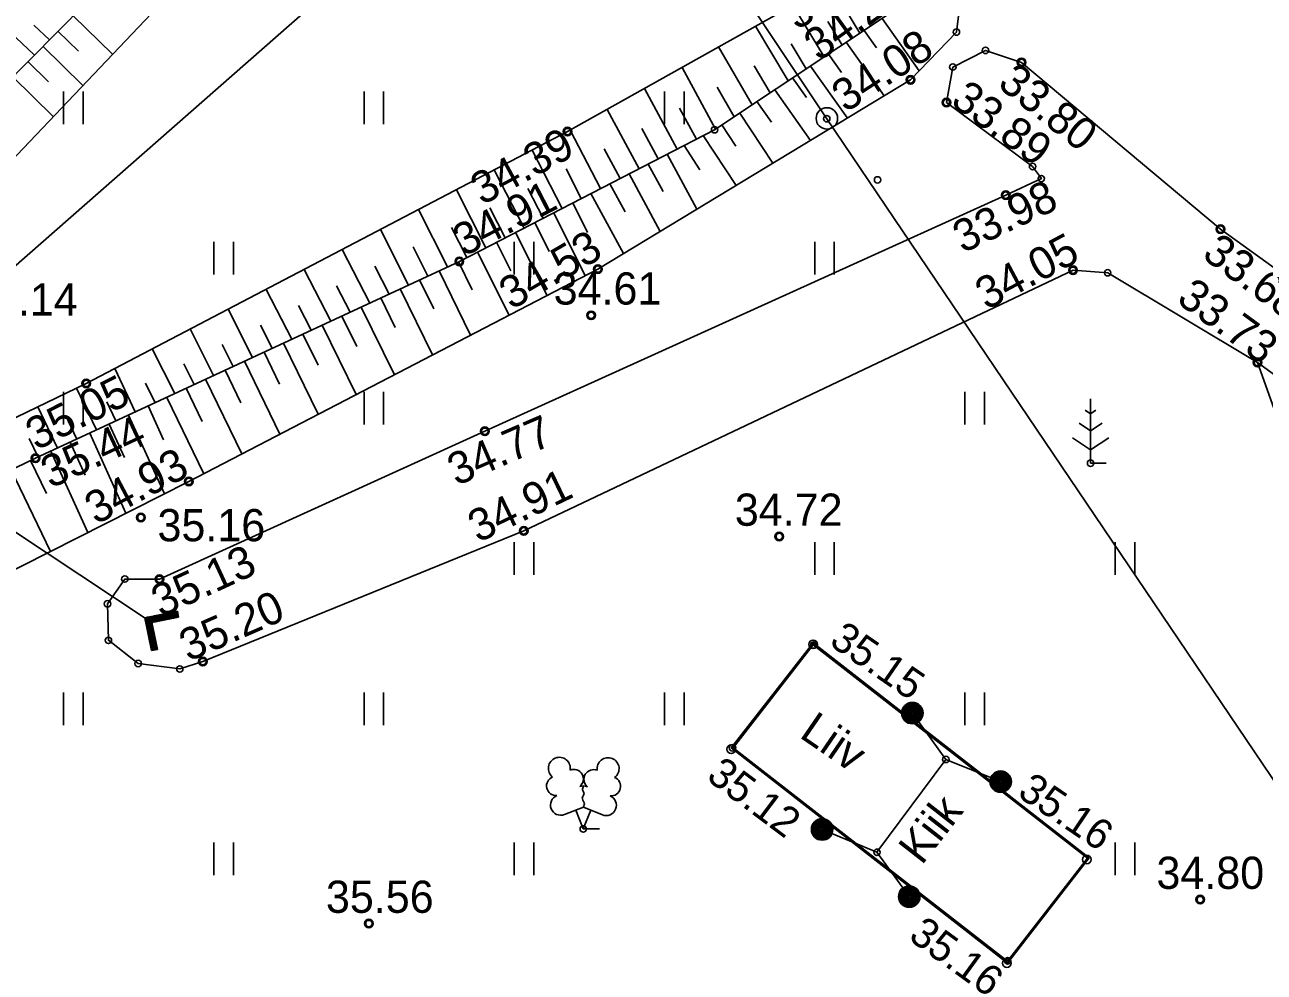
# Model space of a CAD drawing. Extents: x 641898 to 642452, y 6471715 to 6472255.
# Drawn here: x 642038.32 to 642067.2, y 6472115.26 to 6472137.34 of the extents above; entities that cross this region are included whole.
import ezdxf

# ---------------------------------------------------------------- set-up
doc = ezdxf.new("R2010")
doc.units = 0
for name, color, linetype in [('HALJASTUS', 7, 'Continuous'), ('KORGUS-EH2000', 7, 'Continuous'), ('MOOTMPUNKT', 7, 'Continuous'), ('MPOHULIIN', 7, 'Continuous'), ('PIIR', 7, 'Continuous'), ('POST', 7, 'Continuous'), ('PUU', 7, 'Continuous'), ('RAJATIS', 7, 'Continuous'), ('RELJEEF', 7, 'Continuous'), ('TRUUP', 7, 'Continuous'), ('VEEKOGU', 7, 'Continuous')]:
    doc.layers.add(name, color=color, linetype=linetype)

msp = doc.modelspace()

# ---------------------------------------------------------------- linework, layer by layer
at = {"layer": 'HALJASTUS'}
for p, q in [((642039.225, 6472135.782), (642039.225, 6472135.021)), ((642039.68, 6472135.782), (642039.68, 6472135.021)), ((642046.225, 6472135.782), (642046.225, 6472135.021)), ((642046.68, 6472135.782), (642046.68, 6472135.021)), ((642053.225, 6472135.782), (642053.225, 6472135.021)), ((642053.68, 6472135.782), (642053.68, 6472135.021)), ((642042.725, 6472132.282), (642042.725, 6472131.521)), ((642043.18, 6472132.282), (642043.18, 6472131.521)), ((642049.725, 6472132.282), (642049.725, 6472131.521)), ((642050.18, 6472132.282), (642050.18, 6472131.521)), ((642056.725, 6472132.282), (642056.725, 6472131.521)), ((642057.18, 6472132.282), (642057.18, 6472131.521)), ((642039.225, 6472128.782), (642039.225, 6472128.021)), ((642039.68, 6472128.782), (642039.68, 6472128.021)), ((642046.225, 6472128.782), (642046.225, 6472128.021)), ((642046.68, 6472128.782), (642046.68, 6472128.021)), ((642060.225, 6472128.782), (642060.225, 6472128.021)), ((642060.68, 6472128.782), (642060.68, 6472128.021)), ((642049.725, 6472125.282), (642049.725, 6472124.521)), ((642050.18, 6472125.282), (642050.18, 6472124.521)), ((642056.725, 6472125.282), (642056.725, 6472124.521)), ((642057.18, 6472125.282), (642057.18, 6472124.521)), ((642063.725, 6472125.282), (642063.725, 6472124.521)), ((642064.18, 6472125.282), (642064.18, 6472124.521)), ((642039.225, 6472121.782), (642039.225, 6472121.021)), ((642039.68, 6472121.782), (642039.68, 6472121.021)), ((642046.225, 6472121.782), (642046.225, 6472121.021)), ((642046.68, 6472121.782), (642046.68, 6472121.021)), ((642053.225, 6472121.782), (642053.225, 6472121.021)), ((642053.68, 6472121.782), (642053.68, 6472121.021)), ((642060.225, 6472121.782), (642060.225, 6472121.021)), ((642060.68, 6472121.782), (642060.68, 6472121.021)), ((642042.725, 6472118.282), (642042.725, 6472117.521)), ((642043.18, 6472118.282), (642043.18, 6472117.521)), ((642049.725, 6472118.282), (642049.725, 6472117.521)), ((642050.18, 6472118.282), (642050.18, 6472117.521)), ((642063.725, 6472118.282), (642063.725, 6472117.521)), ((642064.18, 6472118.282), (642064.18, 6472117.521))]:
    msp.add_line(p, q, dxfattribs=at)
at = {"layer": 'KORGUS-EH2000'}
for centre in [(642061.545, 6472136.463), (642058.959, 6472136.054), (642059.793, 6472135.528), (642050.967, 6472134.85), (642061.175, 6472133.369), (642066.18, 6472132.576), (642048.445, 6472131.824), (642051.674, 6472131.646), (642062.743, 6472131.619), (642051.516, 6472130.569), (642067.041, 6472129.467), (642039.752, 6472128.982), (642049.039, 6472127.868), (642038.57, 6472127.238), (642042.143, 6472126.699), (642041.025, 6472125.858), (642049.945, 6472125.546), (642055.899, 6472125.415), (642041.457, 6472124.419), (642056.686, 6472122.902), (642042.468, 6472122.501), (642054.779, 6472120.457), (642063.067, 6472117.888), (642065.707, 6472116.954), (642046.338, 6472116.396), (642061.202, 6472115.474)]:
    msp.add_circle(centre, 0.1, dxfattribs=at)
at = {"layer": 'MOOTMPUNKT'}
for centre in [(642060.027, 6472137.169), (642060.703, 6472136.742), (642061.545, 6472136.463), (642059.943, 6472136.354), (642058.959, 6472136.054), (642059.793, 6472135.528), (642057.005, 6472135.15), (642050.967, 6472134.85), (642054.392, 6472134.892), (642061.802, 6472134.036), (642058.189, 6472133.724), (642062.005, 6472133.753), (642061.175, 6472133.369), (642066.18, 6472132.576), (642048.445, 6472131.824), (642051.674, 6472131.646), (642062.743, 6472131.619), (642063.551, 6472131.56), (642051.516, 6472130.569), (642067.041, 6472129.467), (642039.752, 6472128.982), (642049.039, 6472127.868), (642038.57, 6472127.238), (642063.153, 6472127.124), (642042.143, 6472126.699), (642041.025, 6472125.858), (642049.945, 6472125.546), (642055.899, 6472125.415), (642040.649, 6472124.424), (642041.457, 6472124.419), (642040.248, 6472123.847), (642041.198, 6472123.463), (642040.268, 6472122.996), (642056.7, 6472122.885), (642040.961, 6472122.457), (642041.931, 6472122.328), (642042.468, 6472122.501), (642059.001, 6472121.299), (642054.809, 6472120.49), (642059.781, 6472120.221), (642061.057, 6472119.704), (642051.332, 6472118.6), (642056.898, 6472118.589), (642058.176, 6472118.057), (642058.927, 6472117.025), (642065.707, 6472116.954), (642046.338, 6472116.396), (642061.22, 6472115.528)]:
    msp.add_circle(centre, 0.075, dxfattribs=at)
at = {"layer": 'MPOHULIIN'}
msp.add_lwpolyline([(642026.721, 6472180.493), (642057.005, 6472135.15), (642092.759, 6472082.232), (642082.032, 6472055.789), (642066.817, 6472023.473)], dxfattribs=at)
at = {"layer": 'PIIR'}
msp.add_line((642094.72, 6472181.39), (642016.19, 6472112.51), dxfattribs=at)
at = {"layer": 'POST'}
msp.add_circle((642057.008, 6472135.157), 0.25, dxfattribs=at)
at = {"layer": 'PUU'}
for p, q in [((642063.153, 6472128.624), (642063.153, 6472127.124)), ((642063.153, 6472128.274), (642063.029, 6472128.357)), ((642063.277, 6472128.357), (642063.153, 6472128.274)), ((642063.153, 6472127.874), (642062.886, 6472128.052)), ((642063.42, 6472128.052), (642063.153, 6472127.874)), ((642062.729, 6472127.713), (642063.153, 6472127.431)), ((642063.153, 6472127.431), (642063.577, 6472127.713)), ((642063.513, 6472127.124), (642063.153, 6472127.124)), ((642050.892, 6472118.935), (642051.337, 6472119.11)), ((642051.332, 6472118.6), (642051.157, 6472119.04)), ((642051.332, 6472118.6), (642051.512, 6472119.04)), ((642051.337, 6472119.11), (642051.777, 6472118.93)), ((642051.712, 6472118.6), (642051.332, 6472118.6))]:
    msp.add_line(p, q, dxfattribs=at)
msp.add_lwpolyline([(642051.337, 6472119.605), (642051.317, 6472119.53), (642051.317, 6472119.51), (642051.327, 6472119.48), (642051.347, 6472119.445), (642051.352, 6472119.425), (642051.337, 6472119.39), (642051.312, 6472119.34), (642051.307, 6472119.315), (642051.312, 6472119.3), (642051.322, 6472119.27), (642051.357, 6472119.21), (642051.362, 6472119.19), (642051.357, 6472119.17), (642051.342, 6472119.135), (642051.337, 6472119.11)], dxfattribs=at)
for centre, radius, start, end in [((642050.775, 6472120.014), 0.256, 111.5027, 232.5173), ((642050.775, 6472120.014), 0.256, 350.4856, 111.5002), ((642051.911, 6472120.005), 0.256, 67.6168, 188.6314), ((642051.911, 6472120.005), 0.256, 306.5997, 67.6143), ((642050.701, 6472119.603), 0.224, 111.4304, 274.4987), ((642051.11, 6472119.764), 0.224, 308.5041, 111.5725), ((642051.573, 6472119.759), 0.225, 67.7016, 230.5126), ((642051.978, 6472119.593), 0.224, 264.6183, 67.6866), ((642051.336, 6472119.367), 0.237, 66.7655, 111.5015), ((642050.806, 6472119.158), 0.237, 111.5014, 291.5004), ((642051.867, 6472119.15), 0.237, 247.6166, 67.6155)]:
    msp.add_arc(centre, radius, start, end, dxfattribs=at)
at = {"layer": 'RAJATIS'}
msp.add_lwpolyline([(642063.123, 6472117.924), (642061.219, 6472115.477), (642054.782, 6472120.487), (642056.686, 6472122.934)], close=True, dxfattribs=at)
for points in [[(642061.213, 6472115.52), (642054.824, 6472120.492), (642056.692, 6472122.892), (642063.081, 6472117.919), (642061.213, 6472115.52)], [(642059.001, 6472121.299), (642059.781, 6472120.221), (642061.057, 6472119.704)], [(642059.781, 6472120.221), (642058.176, 6472118.057)], [(642056.898, 6472118.589), (642058.176, 6472118.057), (642058.927, 6472117.025)]]:
    msp.add_lwpolyline(points, dxfattribs=at)
for centre, radius in [((642059.001, 6472121.299), 0.25), ((642059.001, 6472121.299), 0.225), ((642059.001, 6472121.299), 0.2), ((642059.001, 6472121.299), 0.175), ((642059.001, 6472121.299), 0.15), ((642059.001, 6472121.299), 0.125), ((642059.001, 6472121.299), 0.1), ((642059.001, 6472121.299), 0.075), ((642059.001, 6472121.299), 0.05), ((642059.001, 6472121.299), 0.025), ((642061.057, 6472119.704), 0.25), ((642061.057, 6472119.704), 0.225), ((642061.057, 6472119.704), 0.2), ((642061.057, 6472119.704), 0.175), ((642061.057, 6472119.704), 0.15), ((642061.057, 6472119.704), 0.125), ((642061.057, 6472119.704), 0.1), ((642061.057, 6472119.704), 0.075), ((642061.057, 6472119.704), 0.05), ((642061.057, 6472119.704), 0.025), ((642056.898, 6472118.589), 0.25), ((642056.898, 6472118.589), 0.225), ((642056.898, 6472118.589), 0.2), ((642056.898, 6472118.589), 0.175), ((642056.898, 6472118.589), 0.15), ((642056.898, 6472118.589), 0.125), ((642056.898, 6472118.589), 0.1), ((642056.898, 6472118.589), 0.075), ((642056.898, 6472118.589), 0.05), ((642056.898, 6472118.589), 0.025), ((642058.927, 6472117.025), 0.25), ((642058.927, 6472117.025), 0.225), ((642058.927, 6472117.025), 0.2), ((642058.927, 6472117.025), 0.175), ((642058.927, 6472117.025), 0.15), ((642058.927, 6472117.025), 0.125), ((642058.927, 6472117.025), 0.1), ((642058.927, 6472117.025), 0.075), ((642058.927, 6472117.025), 0.05), ((642058.927, 6472117.025), 0.025)]:
    msp.add_circle(centre, radius, dxfattribs=at)
at = {"layer": 'RELJEEF'}
for p, q in [((642057.778, 6472137.143), (642057.09, 6472138.285)), ((642056.944, 6472136.589), (642056.217, 6472137.795)), ((642039.444, 6472137.548), (642040.36, 6472136.65)), ((642057.361, 6472136.866), (642057.032, 6472137.412)), ((642058.294, 6472137.486), (642059.159, 6472136.263)), ((642038.541, 6472136.635), (642037.838, 6472137.3)), ((642038.893, 6472136.991), (642038.533, 6472137.33)), ((642039.092, 6472137.193), (642039.575, 6472136.72)), ((642056.107, 6472136.032), (642055.349, 6472137.308)), ((642057.877, 6472137.209), (642058.166, 6472136.8)), ((642038.741, 6472136.837), (642039.671, 6472135.925)), ((642055.265, 6472135.472), (642054.485, 6472136.824)), ((642056.524, 6472136.309), (642056.175, 6472136.896)), ((642057.46, 6472136.932), (642058.344, 6472135.682)), ((642057.044, 6472136.655), (642057.35, 6472136.223)), ((642038.39, 6472136.481), (642038.874, 6472136.006)), ((642054.411, 6472134.905), (642053.633, 6472136.346)), ((642055.69, 6472135.755), (642055.315, 6472136.385)), ((642056.627, 6472136.378), (642057.487, 6472135.163)), ((642038.038, 6472136.126), (642038.982, 6472135.2)), ((642056.211, 6472136.101), (642056.533, 6472135.645)), ((642053.523, 6472134.444), (642052.761, 6472135.856)), ((642054.848, 6472135.195), (642054.45, 6472135.884)), ((642055.794, 6472135.824), (642056.629, 6472134.644)), ((642052.634, 6472133.985), (642051.888, 6472135.367)), ((642053.968, 6472134.673), (642053.577, 6472135.397)), ((642055.378, 6472135.547), (642055.717, 6472135.068)), ((642054.978, 6472135.282), (642055.748, 6472134.111)), ((642051.732, 6472133.52), (642051.029, 6472134.885)), ((642053.079, 6472134.215), (642052.697, 6472134.921)), ((642054.127, 6472134.755), (642054.891, 6472133.593)), ((642054.562, 6472135.005), (642054.887, 6472134.51)), ((642053.681, 6472134.525), (642054.051, 6472133.961)), ((642050.843, 6472133.061), (642050.144, 6472134.42)), ((642052.19, 6472133.756), (642051.817, 6472134.446)), ((642053.288, 6472134.322), (642053.982, 6472133.043)), ((642049.954, 6472132.603), (642049.258, 6472133.956)), ((642051.287, 6472133.29), (642050.93, 6472133.984)), ((642052.844, 6472134.093), (642053.19, 6472133.454)), ((642051.955, 6472133.635), (642052.311, 6472132.977)), ((642052.399, 6472133.864), (642053.126, 6472132.524)), ((642049.062, 6472132.142), (642048.376, 6472133.494)), ((642050.399, 6472132.832), (642050.041, 6472133.527)), ((642051.51, 6472133.405), (642052.269, 6472132.006)), ((642048.167, 6472131.695), (642047.49, 6472133.031)), ((642049.51, 6472132.373), (642049.152, 6472133.07)), ((642051.088, 6472133.188), (642051.432, 6472132.501)), ((642050.644, 6472132.958), (642051.377, 6472131.492)), ((642047.26, 6472131.274), (642046.604, 6472132.567)), ((642048.617, 6472131.913), (642048.26, 6472132.617)), ((642049.755, 6472132.5), (642050.49, 6472131.031)), ((642050.2, 6472132.729), (642050.537, 6472132.054)), ((642047.713, 6472131.484), (642047.368, 6472132.165)), ((642049.311, 6472132.271), (642049.643, 6472131.607)), ((642046.356, 6472130.854), (642045.714, 6472132.101)), ((642048.866, 6472132.041), (642049.602, 6472130.571)), ((642045.449, 6472130.432), (642044.828, 6472131.638)), ((642046.806, 6472131.063), (642046.476, 6472131.713)), ((642047.973, 6472131.605), (642048.708, 6472130.106)), ((642048.427, 6472131.816), (642048.747, 6472131.163)), ((642047.52, 6472131.394), (642047.849, 6472130.723)), ((642044.541, 6472130.011), (642043.942, 6472131.174)), ((642045.902, 6472130.643), (642045.586, 6472131.257)), ((642047.066, 6472131.184), (642047.82, 6472129.646)), ((642043.628, 6472129.587), (642043.061, 6472130.714)), ((642044.995, 6472130.222), (642044.697, 6472130.799)), ((642046.159, 6472130.762), (642046.932, 6472129.185)), ((642046.613, 6472130.973), (642046.951, 6472130.283)), ((642045.705, 6472130.552), (642046.053, 6472129.843)), ((642042.72, 6472129.165), (642042.175, 6472130.25)), ((642044.087, 6472129.8), (642043.808, 6472130.341)), ((642045.252, 6472130.341), (642046.044, 6472128.724)), ((642043.174, 6472129.376), (642042.916, 6472129.889)), ((642044.347, 6472129.921), (642045.154, 6472128.262)), ((642044.801, 6472130.132), (642045.154, 6472129.404)), ((642041.813, 6472128.744), (642041.289, 6472129.786)), ((642043.894, 6472129.71), (642044.255, 6472128.967)), ((642040.895, 6472128.318), (642040.415, 6472129.329)), ((642042.267, 6472128.955), (642042.023, 6472129.44)), ((642042.986, 6472129.289), (642043.356, 6472128.529)), ((642043.44, 6472129.5), (642044.266, 6472127.801)), ((642067.041, 6472129.467), (642067.041, 6472129.467)), ((642041.359, 6472128.533), (642041.13, 6472128.99)), ((642042.533, 6472129.078), (642043.378, 6472127.34)), ((642039.988, 6472127.897), (642039.525, 6472128.872)), ((642042.079, 6472128.868), (642042.456, 6472128.092)), ((642039.081, 6472127.475), (642038.625, 6472128.437)), ((642040.442, 6472128.107), (642040.229, 6472128.556)), ((642041.194, 6472128.456), (642041.552, 6472127.666)), ((642041.626, 6472128.657), (642042.49, 6472126.879)), ((642039.535, 6472127.686), (642039.325, 6472128.127)), ((642040.74, 6472128.246), (642041.572, 6472126.41)), ((642039.833, 6472127.825), (642040.678, 6472125.959)), ((642040.287, 6472128.035), (642040.641, 6472127.253)), ((642038.628, 6472127.265), (642038.422, 6472127.698)), ((642039.38, 6472127.614), (642039.73, 6472126.841)), ((642038.926, 6472127.403), (642039.785, 6472125.507)), ((642038.005, 6472126.965), (642038.919, 6472125.069)), ((642038.455, 6472127.183), (642038.823, 6472126.42))]:
    msp.add_line(p, q, dxfattribs=at)
for points in [[(642006.634, 6472115.624), (642008.538, 6472116.55), (642017.993, 6472121.511), (642028.623, 6472127.021), (642032.534, 6472129.313), (642035.29, 6472131.318), (642042.314, 6472138.705), (642049.959, 6472146.539), (642050.735, 6472147.496), (642050.679, 6472148.514), (642050.124, 6472149.08), (642049.261, 6472148.828), (642043.691, 6472143.566), (642035.664, 6472134.973), (642031.363, 6472131.489), (642028.508, 6472130.403), (642018.766, 6472130.302), (642010.574, 6472130.456), (642006.315, 6472130.011), (642002.538, 6472126.116), (641998.265, 6472121.279), (641996.189, 6472118.754)], [(642049.525, 6472147.752), (642033.209, 6472131.238), (642029.368, 6472128.57), (642019.347, 6472123.425), (642009.733, 6472118.353), (642006.276, 6472116.303), (642004.319, 6472114.766), (642003.015, 6472112.887), (642001.569, 6472108.88), (641999.049, 6472106.763)], [(642123.464, 6472142.672), (642123.047, 6472142.573), (642120.087, 6472139.168), (642115.741, 6472134.233), (642111.73, 6472129.44), (642104.866, 6472121.549), (642098.208, 6472113.834), (642093.661, 6472110.303), (642090.857, 6472109.171), (642088.254, 6472108.802), (642086.484, 6472109.321), (642083.076, 6472111.816), (642080.848, 6472115.189), (642078.612, 6472117.548), (642074.153, 6472119.305), (642067.802, 6472127.345), (642067.041, 6472129.467)], [(642009.422, 6472112.742), (642011.469, 6472114.538), (642021.273, 6472119.831), (642030.743, 6472124.628), (642039.752, 6472128.982), (642050.967, 6472134.85), (642058.208, 6472138.912), (642059.402, 6472139.059), (642060.171, 6472138.313), (642060.027, 6472137.169), (642058.959, 6472136.054), (642051.674, 6472131.646), (642042.143, 6472126.699), (642035.655, 6472123.419), (642032.765, 6472119.235), (642026.028, 6472115.246), (642020.049, 6472113.422), (642015.898, 6472110.337), (642013.512, 6472106.135), (642008.467, 6472103.33), (642003.93, 6472101.516)], [(642058.721, 6472137.77), (642054.392, 6472134.892), (642048.445, 6472131.824), (642038.57, 6472127.238), (642029.307, 6472122.768), (642018.627, 6472117.511), (642010.755, 6472113.076), (642008.847, 6472109.72), (642006.969, 6472107.208), (642003.529, 6472102.174)]]:
    msp.add_lwpolyline(points, dxfattribs=at)
at = {"layer": 'TRUUP'}
for p, q in [((642041.876, 6472123.675), (642041.114, 6472123.518)), ((642041.114, 6472123.518), (642041.27, 6472122.756)), ((642041.417, 6472123.435), (642041.114, 6472123.517)), ((642041.363, 6472123.424), (642041.12, 6472123.49)), ((642041.472, 6472123.446), (642041.166, 6472123.529)), ((642041.891, 6472123.605), (642041.198, 6472123.463)), ((642041.526, 6472123.458), (642041.221, 6472123.54)), ((642041.58, 6472123.469), (642041.275, 6472123.551)), ((642041.905, 6472123.535), (642041.282, 6472123.408)), ((642041.635, 6472123.48), (642041.329, 6472123.563)), ((642041.689, 6472123.491), (642041.384, 6472123.574)), ((642041.744, 6472123.502), (642041.438, 6472123.585)), ((642041.798, 6472123.513), (642041.493, 6472123.596)), ((642041.853, 6472123.525), (642041.547, 6472123.607)), ((642041.905, 6472123.536), (642041.602, 6472123.618)), ((642041.899, 6472123.564), (642041.656, 6472123.63)), ((642041.894, 6472123.591), (642041.71, 6472123.641)), ((642041.888, 6472123.619), (642041.765, 6472123.652)), ((642041.882, 6472123.646), (642041.819, 6472123.663)), ((642041.905, 6472123.535), (642041.876, 6472123.675)), ((642041.308, 6472123.413), (642041.125, 6472123.462)), ((642041.285, 6472123.393), (642041.131, 6472123.435)), ((642041.291, 6472123.366), (642041.137, 6472123.408)), ((642041.296, 6472123.339), (642041.142, 6472123.38)), ((642041.302, 6472123.311), (642041.148, 6472123.353)), ((642041.307, 6472123.284), (642041.154, 6472123.325)), ((642041.313, 6472123.256), (642041.159, 6472123.298)), ((642041.319, 6472123.229), (642041.165, 6472123.271)), ((642041.324, 6472123.201), (642041.17, 6472123.243)), ((642041.33, 6472123.174), (642041.176, 6472123.216)), ((642041.198, 6472123.463), (642041.34, 6472122.77)), ((642041.282, 6472123.408), (642041.41, 6472122.785)), ((642041.336, 6472123.147), (642041.182, 6472123.188)), ((642041.341, 6472123.119), (642041.187, 6472123.161)), ((642041.347, 6472123.092), (642041.193, 6472123.133)), ((642041.352, 6472123.064), (642041.199, 6472123.106)), ((642041.358, 6472123.037), (642041.204, 6472123.079)), ((642041.364, 6472123.009), (642041.21, 6472123.051)), ((642041.369, 6472122.982), (642041.215, 6472123.024)), ((642041.375, 6472122.955), (642041.221, 6472122.996)), ((642041.381, 6472122.927), (642041.227, 6472122.969)), ((642041.386, 6472122.9), (642041.232, 6472122.941)), ((642041.392, 6472122.872), (642041.238, 6472122.914)), ((642041.397, 6472122.845), (642041.244, 6472122.887)), ((642041.403, 6472122.817), (642041.249, 6472122.859)), ((642041.409, 6472122.79), (642041.255, 6472122.832)), ((642041.366, 6472122.776), (642041.26, 6472122.804)), ((642041.312, 6472122.765), (642041.266, 6472122.777)), ((642041.41, 6472122.785), (642041.27, 6472122.756))]:
    msp.add_line(p, q, dxfattribs=at)
msp.add_lwpolyline([(642026.163, 6472133.431), (642041.198, 6472123.463)], dxfattribs=at)
at = {"layer": 'VEEKOGU'}
msp.add_lwpolyline([(642071.926, 6472125.922), (642067.041, 6472129.467), (642063.551, 6472131.56), (642062.743, 6472131.619), (642049.945, 6472125.546), (642042.468, 6472122.501), (642041.931, 6472122.328), (642040.961, 6472122.457), (642040.268, 6472122.996), (642040.248, 6472123.847), (642040.649, 6472124.424), (642041.457, 6472124.419), (642049.039, 6472127.868), (642061.175, 6472133.369), (642062.005, 6472133.753), (642061.802, 6472134.036), (642059.793, 6472135.528), (642059.943, 6472136.354), (642060.703, 6472136.742), (642061.545, 6472136.463), (642066.18, 6472132.576), (642073.243, 6472127.488)], dxfattribs=at)

# ---------------------------------------------------------------- texts
at = {"layer": 'KORGUS-EH2000'}
for s, height, rotation, p in [('34.03', 0.75, 31.8541, (642056.312, 6472137.196)), ('34.27', 0.75, 35.8776, (642056.829, 6472136.467)), ('34.08', 0.75, 33.1013, (642057.445, 6472135.278)), ('33.80', 0.75, 321.5319, (642060.957, 6472135.912)), ('33.89', 0.75, 323.738, (642059.86, 6472135.492)), ('34.39', 0.75, 28.4359, (642048.976, 6472133.123)), ('34.91', 0.75, 27.2518, (642048.549, 6472131.925)), ('33.98', 0.75, 25.1117, (642060.173, 6472132.007)), ('34.53', 0.75, 30.1134, (642049.659, 6472130.684)), ('34.05', 0.75, 28.0919, (642060.73, 6472130.678)), ('33.68', 0.75, 323.4732, (642065.72, 6472131.926)), ('33.73', 0.75, 323.7391, (642065.127, 6472130.885)), ('35.05', 0.75, 26.8307, (642038.591, 6472127.41)), ('35.44', 0.75, 24.9474, (642038.923, 6472126.524)), ('34.77', 0.75, 23.3835, (642048.377, 6472126.585)), ('34.93', 0.75, 27.8301, (642039.978, 6472125.681)), ('34.91', 0.75, 25.6878, (642048.882, 6472125.26)), ('35.13', 0.75, 24.698, (642041.493, 6472123.522)), ('35.20', 0.75, 23.6968, (642042.134, 6472122.489)), ('35.15', 0.7, 325.4473, (642057.036, 6472122.902)), ('35.12', 0.7, 323.1047, (642054.174, 6472119.767)), ('35.16', 0.7, 325.9893, (642061.419, 6472119.375)), ('35.16', 0.7, 323.9474, (642058.882, 6472116.04))]:
    msp.add_text(s, height=height, rotation=rotation, dxfattribs=at).set_placement(p)
for s, p in [('34.61', (642050.642, 6472130.819)), ('35.14', (642037.044, 6472130.564)), ('34.72', (642054.864, 6472125.665)), ('35.16', (642041.412, 6472125.304)), ('34.80', (642064.687, 6472117.204)), ('35.56', (642045.336, 6472116.646))]:
    msp.add_text(s, height=0.75, dxfattribs=at).set_placement(p)
at = {"layer": 'RAJATIS'}
for s, rotation, p in [('Liiv', 325.5761, (642056.341, 6472120.752)), ('Kiik', 52.04, (642059.218, 6472117.737))]:
    msp.add_text(s, height=0.75, rotation=rotation, dxfattribs=at).set_placement(p)

doc.saveas('drawing.dxf')
